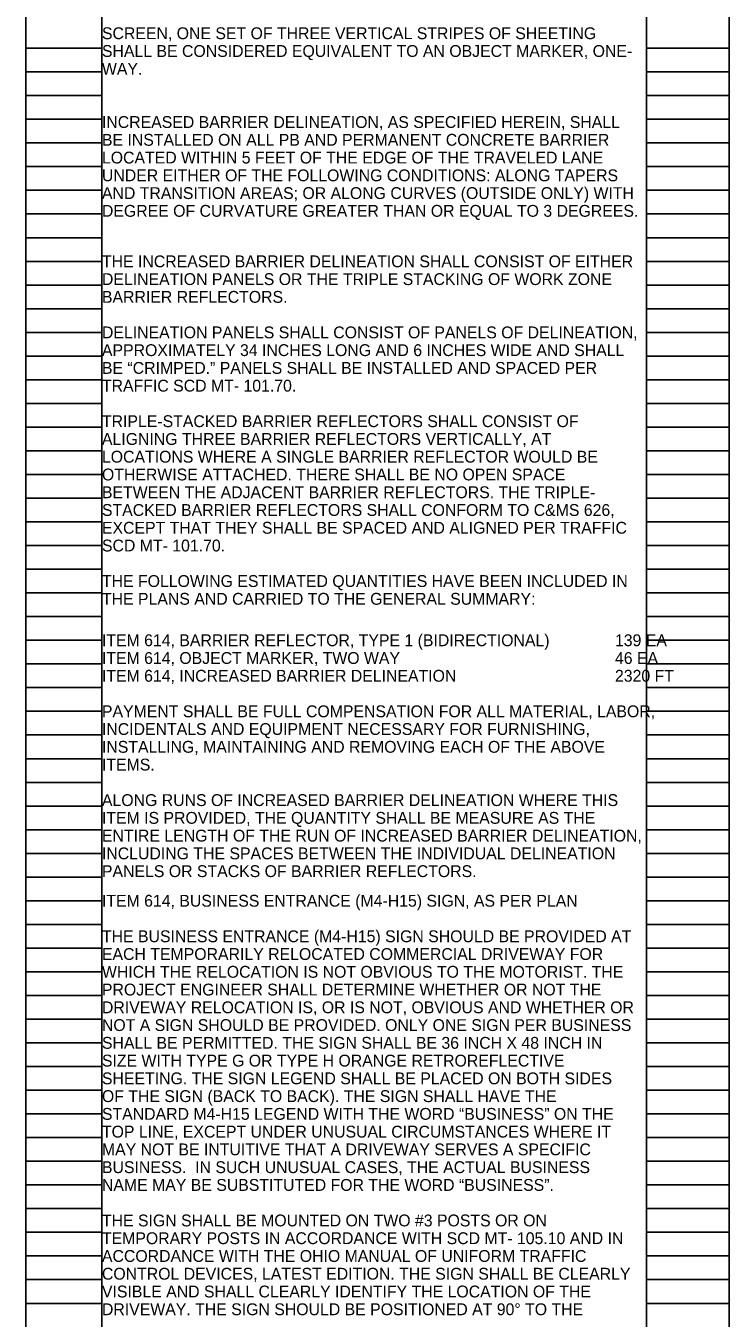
# Model space of a CAD drawing. Extents: x 11124 to 11156, y 1608 to 1730.
# Drawn here: x 11125.9 to 11134.22, y 1668.99 to 1684.27 of the extents above; entities that cross this region are included whole.
import ezdxf

# ---------------------------------------------------------------- set-up
doc = ezdxf.new("R2010")
doc.units = 0
doc.layers.add('SC_Scratch1', color=7, linetype='Continuous')
doc.layers.add('SH_Text', color=7, linetype='Continuous')

msp = doc.modelspace()

# ---------------------------------------------------------------- linework, layer by layer
at = {"layer": 'SC_Scratch1'}
for p, q in [((11125.896, 1669.729), (11125.896, 1689.889)), ((11126.796, 1669.729), (11126.796, 1689.889)), ((11133.236, 1669.729), (11133.236, 1689.889)), ((11134.216, 1669.729), (11134.216, 1689.889)), ((11125.896, 1684.009), (11126.796, 1684.009)), ((11133.236, 1684.009), (11134.216, 1684.009)), ((11125.896, 1683.729), (11126.796, 1683.729)), ((11133.236, 1683.729), (11134.216, 1683.729)), ((11125.896, 1683.449), (11126.796, 1683.449)), ((11133.236, 1683.449), (11134.216, 1683.449)), ((11125.896, 1683.169), (11126.796, 1683.169)), ((11133.236, 1683.169), (11134.216, 1683.169)), ((11125.896, 1682.889), (11126.796, 1682.889)), ((11133.236, 1682.889), (11134.216, 1682.889)), ((11125.896, 1682.609), (11126.796, 1682.609)), ((11133.236, 1682.609), (11134.216, 1682.609)), ((11125.896, 1682.329), (11126.796, 1682.329)), ((11133.236, 1682.329), (11134.216, 1682.329)), ((11125.896, 1682.049), (11126.796, 1682.049)), ((11133.236, 1682.049), (11134.216, 1682.049)), ((11125.896, 1681.769), (11126.796, 1681.769)), ((11133.236, 1681.769), (11134.216, 1681.769)), ((11125.896, 1681.489), (11126.796, 1681.489)), ((11133.236, 1681.489), (11134.216, 1681.489)), ((11125.896, 1681.209), (11126.796, 1681.209)), ((11133.236, 1681.209), (11134.216, 1681.209)), ((11125.896, 1680.929), (11126.796, 1680.929)), ((11133.236, 1680.929), (11134.216, 1680.929)), ((11125.896, 1680.649), (11126.796, 1680.649)), ((11133.236, 1680.649), (11134.216, 1680.649)), ((11125.896, 1680.369), (11126.796, 1680.369)), ((11133.236, 1680.369), (11134.216, 1680.369)), ((11125.896, 1680.089), (11126.796, 1680.089)), ((11133.236, 1680.089), (11134.216, 1680.089)), ((11125.896, 1679.809), (11126.796, 1679.809)), ((11133.236, 1679.809), (11134.216, 1679.809)), ((11125.896, 1679.529), (11126.796, 1679.529)), ((11133.236, 1679.529), (11134.216, 1679.529)), ((11125.896, 1679.249), (11126.796, 1679.249)), ((11133.236, 1679.249), (11134.216, 1679.249)), ((11125.896, 1678.969), (11126.796, 1678.969)), ((11133.236, 1678.969), (11134.216, 1678.969)), ((11125.896, 1678.689), (11126.796, 1678.689)), ((11133.236, 1678.689), (11134.216, 1678.689)), ((11125.896, 1678.409), (11126.796, 1678.409)), ((11133.236, 1678.409), (11134.216, 1678.409)), ((11125.896, 1678.129), (11126.796, 1678.129)), ((11133.236, 1678.129), (11134.216, 1678.129)), ((11125.896, 1677.849), (11126.796, 1677.849)), ((11133.236, 1677.849), (11134.216, 1677.849)), ((11125.896, 1677.569), (11126.796, 1677.569)), ((11133.236, 1677.569), (11134.216, 1677.569)), ((11125.896, 1677.289), (11126.796, 1677.289)), ((11133.236, 1677.289), (11134.216, 1677.289)), ((11125.896, 1677.009), (11126.796, 1677.009)), ((11133.236, 1677.009), (11134.216, 1677.009)), ((11125.896, 1676.729), (11126.796, 1676.729)), ((11133.236, 1676.729), (11134.216, 1676.729)), ((11125.896, 1676.449), (11126.796, 1676.449)), ((11133.236, 1676.449), (11134.216, 1676.449)), ((11125.896, 1676.169), (11126.796, 1676.169)), ((11133.236, 1676.169), (11134.216, 1676.169)), ((11125.896, 1675.889), (11126.796, 1675.889)), ((11133.236, 1675.889), (11134.216, 1675.889)), ((11125.896, 1675.609), (11126.796, 1675.609)), ((11133.236, 1675.609), (11134.216, 1675.609)), ((11125.896, 1675.329), (11126.796, 1675.329)), ((11133.236, 1675.329), (11134.216, 1675.329)), ((11125.896, 1675.049), (11126.796, 1675.049)), ((11133.236, 1675.049), (11134.216, 1675.049)), ((11125.896, 1674.769), (11126.796, 1674.769)), ((11133.236, 1674.769), (11134.216, 1674.769)), ((11125.896, 1674.489), (11126.796, 1674.489)), ((11133.236, 1674.489), (11134.216, 1674.489)), ((11125.896, 1674.209), (11126.796, 1674.209)), ((11133.236, 1674.209), (11134.216, 1674.209)), ((11125.896, 1673.929), (11126.796, 1673.929)), ((11133.236, 1673.929), (11134.216, 1673.929)), ((11125.896, 1673.649), (11126.796, 1673.649)), ((11133.236, 1673.649), (11134.216, 1673.649)), ((11125.896, 1673.369), (11126.796, 1673.369)), ((11133.236, 1673.369), (11134.216, 1673.369)), ((11125.896, 1673.089), (11126.796, 1673.089)), ((11133.236, 1673.089), (11134.216, 1673.089)), ((11125.896, 1672.809), (11126.796, 1672.809)), ((11133.236, 1672.809), (11134.216, 1672.809)), ((11125.896, 1672.529), (11126.796, 1672.529)), ((11133.236, 1672.529), (11134.216, 1672.529)), ((11125.896, 1672.249), (11126.796, 1672.249)), ((11133.236, 1672.249), (11134.216, 1672.249)), ((11125.896, 1671.969), (11126.796, 1671.969)), ((11133.236, 1671.969), (11134.216, 1671.969)), ((11125.896, 1671.689), (11126.796, 1671.689)), ((11133.236, 1671.689), (11134.216, 1671.689)), ((11125.896, 1671.409), (11126.796, 1671.409)), ((11133.236, 1671.409), (11134.216, 1671.409)), ((11125.896, 1671.129), (11126.796, 1671.129)), ((11133.236, 1671.129), (11134.216, 1671.129)), ((11125.896, 1670.849), (11126.796, 1670.849)), ((11133.236, 1670.849), (11134.216, 1670.849)), ((11125.896, 1670.569), (11126.796, 1670.569)), ((11133.236, 1670.569), (11134.216, 1670.569)), ((11125.896, 1670.289), (11126.796, 1670.289)), ((11133.236, 1670.289), (11134.216, 1670.289)), ((11125.896, 1670.009), (11126.796, 1670.009)), ((11133.236, 1670.009), (11134.216, 1670.009)), ((11125.896, 1669.729), (11126.796, 1669.729)), ((11125.896, 1649.569), (11125.896, 1669.729)), ((11125.896, 1669.729), (11126.796, 1669.729)), ((11126.796, 1649.569), (11126.796, 1669.729)), ((11133.236, 1669.729), (11134.216, 1669.729)), ((11133.236, 1649.569), (11133.236, 1669.729)), ((11133.236, 1669.729), (11134.216, 1669.729)), ((11134.216, 1649.569), (11134.216, 1669.729)), ((11125.896, 1669.449), (11126.796, 1669.449)), ((11133.236, 1669.449), (11134.216, 1669.449)), ((11125.896, 1669.169), (11126.796, 1669.169)), ((11133.236, 1669.169), (11134.216, 1669.169))]:
    msp.add_line(p, q, dxfattribs=at)

# ---------------------------------------------------------------- texts
at = {"layer": 'SH_Text'}
for s, p in [('SCREEN, ONE SET OF THREE VERTICAL STRIPES OF SHEETING', (11126.796, 1684.116)), ('SHALL BE CONSIDERED EQUIVALENT TO AN OBJECT MARKER, ONE-', (11126.796, 1683.906)), ('WAY.', (11126.796, 1683.696)), ('INCREASED BARRIER DELINEATION, AS SPECIFIED HEREIN, SHALL ', (11126.796, 1683.066)), ('BE INSTALLED ON ALL PB AND PERMANENT CONCRETE BARRIER ', (11126.796, 1682.856)), ('LOCATED WITHIN 5 FEET OF THE EDGE OF THE TRAVELED LANE ', (11126.796, 1682.646)), ('UNDER EITHER OF THE FOLLOWING CONDITIONS: ALONG TAPERS ', (11126.796, 1682.436)), ('AND TRANSITION AREAS; OR ALONG CURVES (OUTSIDE ONLY) WITH ', (11126.796, 1682.226)), ('DEGREE OF CURVATURE GREATER THAN OR EQUAL TO 3 DEGREES.', (11126.796, 1682.016)), ('THE INCREASED BARRIER DELINEATION SHALL CONSIST OF EITHER ', (11126.796, 1681.419)), ('DELINEATION PANELS OR THE TRIPLE STACKING OF WORK ZONE ', (11126.796, 1681.209)), ('BARRIER REFLECTORS.', (11126.796, 1680.999)), ('DELINEATION PANELS SHALL CONSIST OF PANELS OF DELINEATION, ', (11126.796, 1680.579)), ('APPROXIMATELY 34 INCHES LONG AND 6 INCHES WIDE AND SHALL ', (11126.796, 1680.369)), ('BE “CRIMPED.” PANELS SHALL BE INSTALLED AND SPACED PER ', (11126.796, 1680.159)), ('TRAFFIC SCD MT- 101.70.', (11126.796, 1679.949)), ('TRIPLE-STACKED BARRIER REFLECTORS SHALL CONSIST OF ', (11126.796, 1679.529)), ('ALIGNING THREE BARRIER REFLECTORS VERTICALLY, AT ', (11126.796, 1679.319)), ('LOCATIONS WHERE A SINGLE BARRIER REFLECTOR WOULD BE ', (11126.796, 1679.109)), ('OTHERWISE ATTACHED. THERE SHALL BE NO OPEN SPACE ', (11126.796, 1678.899)), ('BETWEEN THE ADJACENT BARRIER REFLECTORS. THE TRIPLE-', (11126.796, 1678.689)), ('STACKED BARRIER REFLECTORS SHALL CONFORM TO C&MS 626, ', (11126.796, 1678.479)), ('EXCEPT THAT THEY SHALL BE SPACED AND ALIGNED PER TRAFFIC ', (11126.796, 1678.269)), ('SCD MT- 101.70.', (11126.796, 1678.059)), ('THE FOLLOWING ESTIMATED QUANTITIES HAVE BEEN INCLUDED IN ', (11126.796, 1677.639)), ('THE PLANS AND CARRIED TO THE GENERAL SUMMARY:', (11126.796, 1677.429)), ('ITEM 614, BARRIER REFLECTOR, TYPE 1 (BIDIRECTIONAL)', (11126.796, 1676.939)), ('139 EA', (11132.865, 1676.939)), ('ITEM 614, OBJECT MARKER, TWO WAY', (11126.796, 1676.729)), ('46 EA', (11132.865, 1676.729)), ('ITEM 614, INCREASED BARRIER DELINEATION', (11126.796, 1676.519)), ('2320 FT', (11132.865, 1676.519)), ('PAYMENT SHALL BE FULL COMPENSATION FOR ALL MATERIAL, LABOR, ', (11126.796, 1676.099)), ('INCIDENTALS AND EQUIPMENT NECESSARY FOR FURNISHING, ', (11126.796, 1675.889)), ('INSTALLING, MAINTAINING AND REMOVING EACH OF THE ABOVE ', (11126.796, 1675.679)), ('ITEMS.', (11126.796, 1675.469)), ('ALONG RUNS OF INCREASED BARRIER DELINEATION WHERE THIS ', (11126.796, 1675.049)), ('ITEM IS PROVIDED, THE QUANTITY SHALL BE MEASURE AS THE ', (11126.796, 1674.839)), ('ENTIRE LENGTH OF THE RUN OF INCREASED BARRIER DELINEATION, ', (11126.796, 1674.629)), ('INCLUDING THE SPACES BETWEEN THE INDIVIDUAL DELINEATION ', (11126.796, 1674.419)), ('PANELS OR STACKS OF BARRIER REFLECTORS.', (11126.796, 1674.209)), ('ITEM 614, BUSINESS ENTRANCE (M4-H15) SIGN, AS PER PLAN', (11126.796, 1673.859)), ('THE BUSINESS ENTRANCE (M4-H15) SIGN SHOULD BE PROVIDED AT ', (11126.796, 1673.439)), ('EACH TEMPORARILY RELOCATED COMMERCIAL DRIVEWAY FOR ', (11126.796, 1673.229)), ('WHICH THE RELOCATION IS NOT OBVIOUS TO THE MOTORIST. THE ', (11126.796, 1673.019)), ('PROJECT ENGINEER SHALL DETERMINE WHETHER OR NOT THE ', (11126.796, 1672.809)), ('DRIVEWAY RELOCATION IS, OR IS NOT, OBVIOUS AND WHETHER OR ', (11126.796, 1672.599)), ('NOT A SIGN SHOULD BE PROVIDED. ONLY ONE SIGN PER BUSINESS ', (11126.796, 1672.389)), ('SHALL BE PERMITTED. THE SIGN SHALL BE 36 INCH X 48 INCH IN ', (11126.796, 1672.179)), ('SIZE WITH TYPE G OR TYPE H ORANGE RETROREFLECTIVE ', (11126.796, 1671.969)), ('SHEETING. THE SIGN LEGEND SHALL BE PLACED ON BOTH SIDES ', (11126.796, 1671.759)), ('OF THE SIGN (BACK TO BACK). THE SIGN SHALL HAVE THE ', (11126.796, 1671.549)), ('STANDARD M4-H15 LEGEND WITH THE WORD “BUSINESS” ON THE ', (11126.796, 1671.339)), ('TOP LINE, EXCEPT UNDER UNUSUAL CIRCUMSTANCES WHERE IT ', (11126.796, 1671.129)), ('MAY NOT BE INTUITIVE THAT A DRIVEWAY SERVES A SPECIFIC ', (11126.796, 1670.919)), ('BUSINESS.  IN SUCH UNUSUAL CASES, THE ACTUAL BUSINESS ', (11126.796, 1670.709)), ('NAME MAY BE SUBSTITUTED FOR THE WORD “BUSINESS”.', (11126.796, 1670.499)), ('THE SIGN SHALL BE MOUNTED ON TWO #3 POSTS OR ON ', (11126.796, 1670.079)), ('TEMPORARY POSTS IN ACCORDANCE WITH SCD MT- 105.10 AND IN ', (11126.796, 1669.869)), ('ACCORDANCE WITH THE OHIO MANUAL OF UNIFORM TRAFFIC ', (11126.796, 1669.659)), ('CONTROL DEVICES, LATEST EDITION. THE SIGN SHALL BE CLEARLY ', (11126.796, 1669.449)), ('VISIBLE AND SHALL CLEARLY IDENTIFY THE LOCATION OF THE ', (11126.796, 1669.239)), ('DRIVEWAY. THE SIGN SHOULD BE POSITIONED AT 90° TO THE ', (11126.796, 1669.029))]:
    msp.add_text(s, height=0.14, dxfattribs=at).set_placement(p)

doc.saveas('drawing.dxf')
